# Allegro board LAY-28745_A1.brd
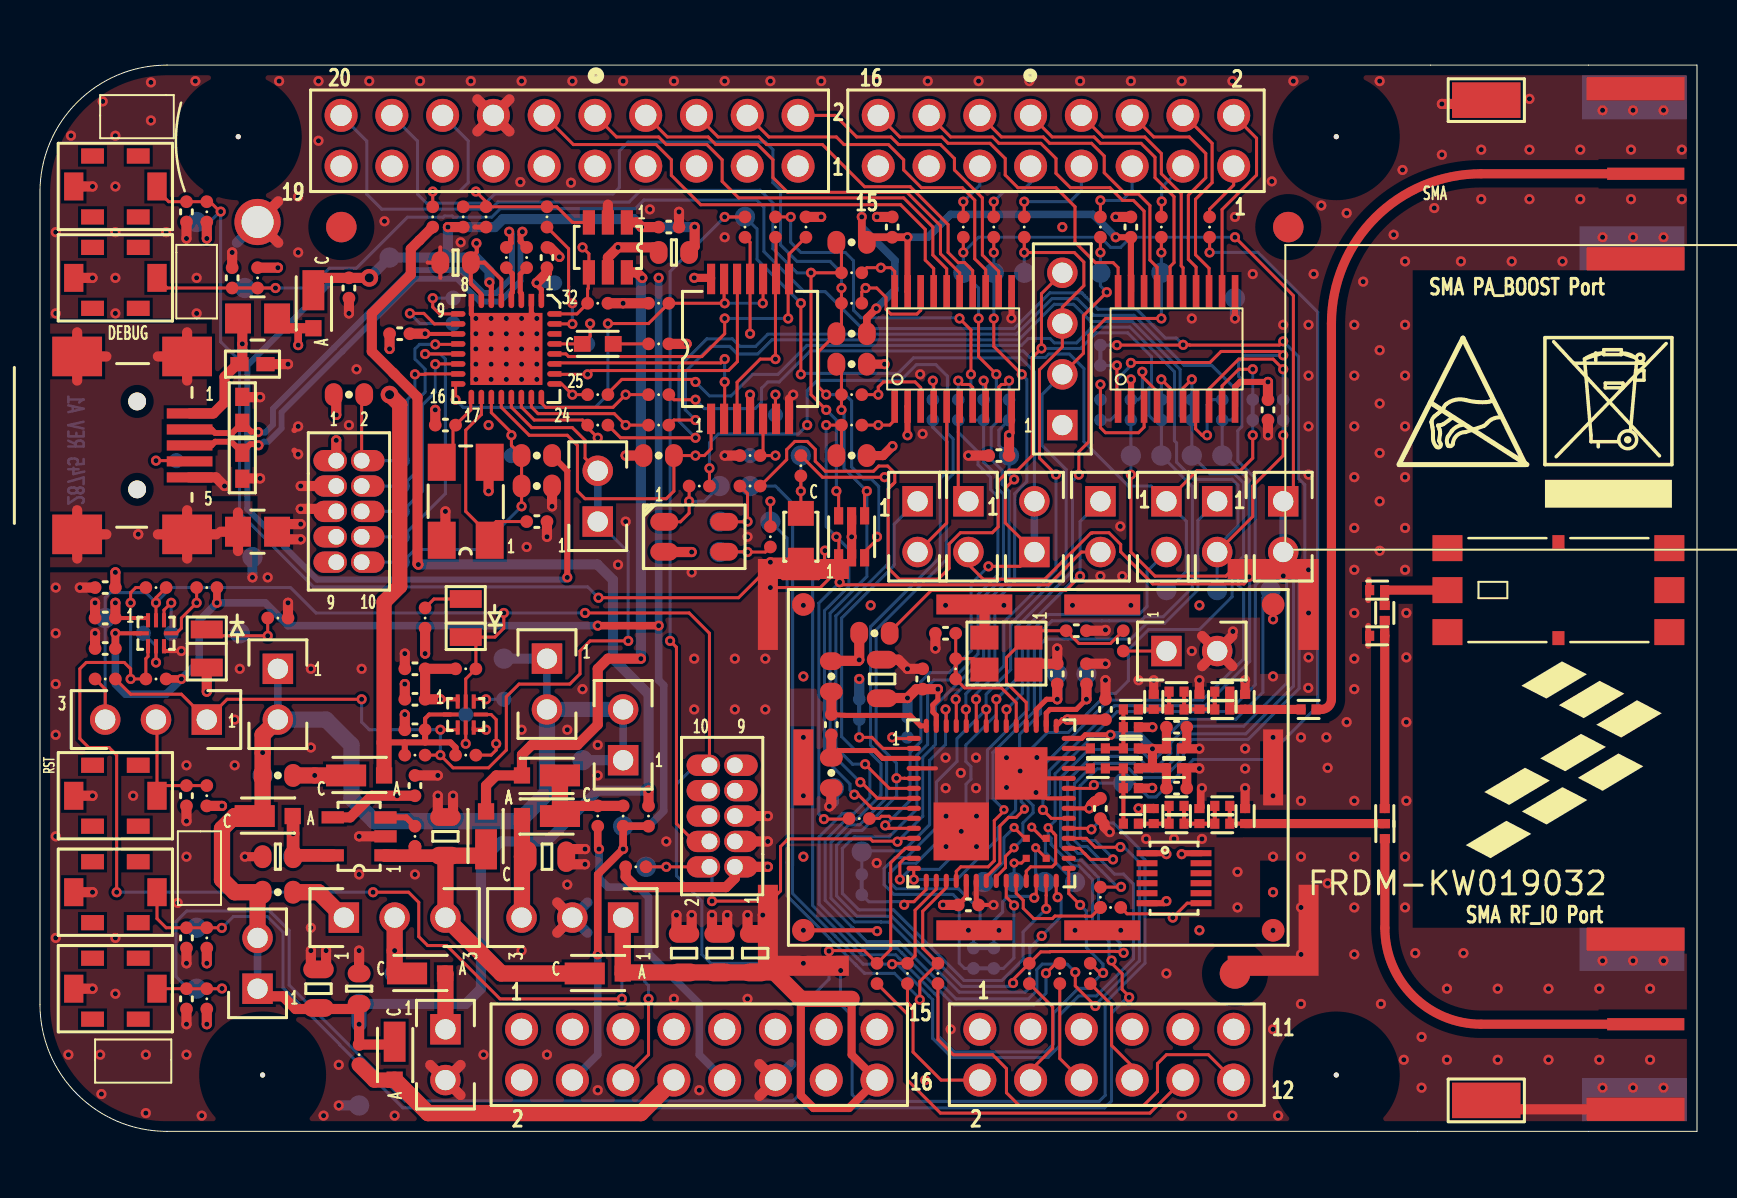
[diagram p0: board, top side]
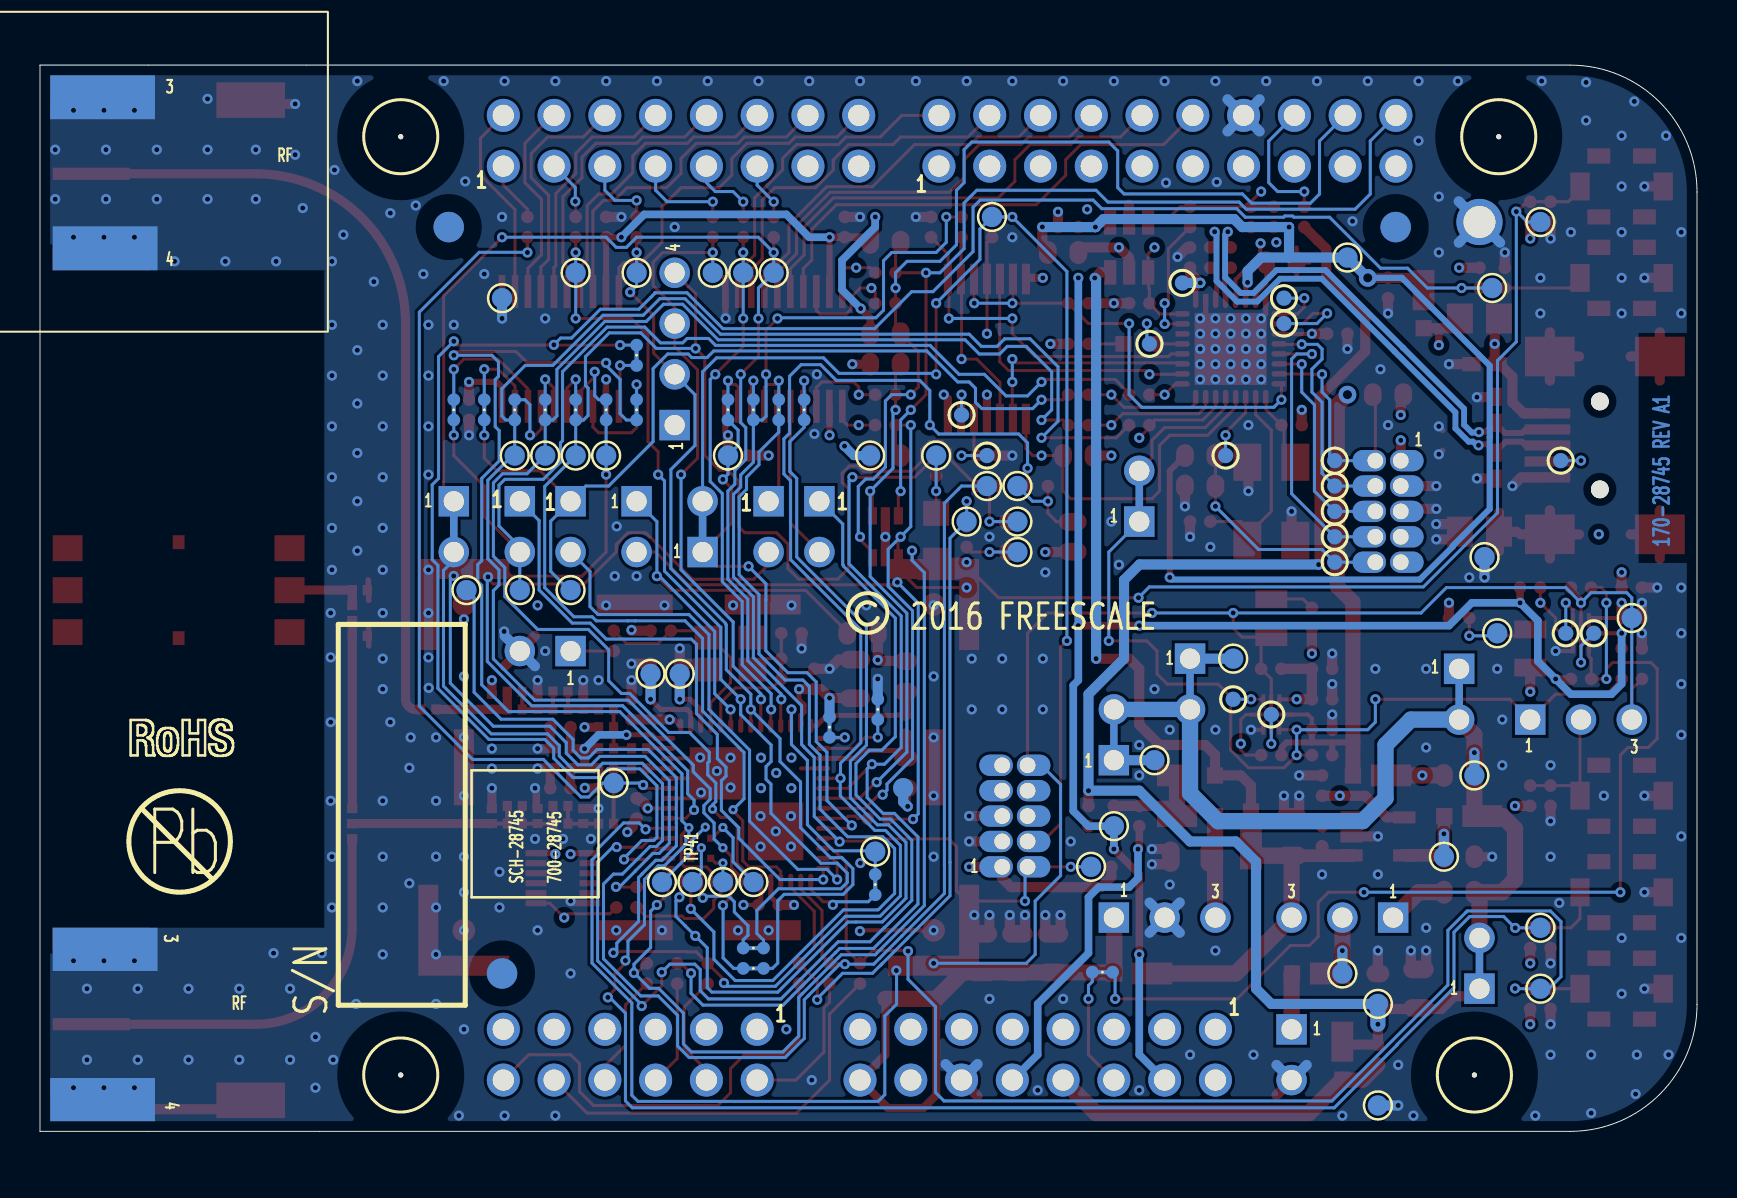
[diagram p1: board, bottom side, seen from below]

Outline 82.89 x 53.34 mm; copper layers: TOP, GND, PWR, BOTTOM. Coordinates in mm from the lower left corner of the outline.
Outline path: 0,46.99 arc(1.86,51.48) 6.35,53.34 82.89,53.34 82.89,0 6.35,0 arc(1.86,1.86) 0,6.35 0,46.99

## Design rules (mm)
net group SDA_USB_CONN_D: nets SDA_USB_CONN_DN SDA_USB_CONN_DP
net group SDA_USB_D: nets SDA_USB_DN SDA_USB_DP
net group GA[0:7]: nets SWD_CLK_TGTMCU
net group GC[0:15]: nets RESET_TGTMCU_B
net group POWER: nets 5V_USB IO_REF N23497733 N23735993 N23818123 N23869363 N23918308 N23977839 N23977884 N23977917 N23977919 N23978170 N23978342 P3V3 P3V3_LDO P5-9V_VIN P5V P5V0_SDA_USB_CONN_VBUS P5V_SDA SDA_USB_VOUT33 SDA_USBSHIELD V_EXT V_MCU VR_ANA VR_DIG VR_PA
net group RF_7CLR: nets N23870337 N23870339 N23870349 N23870369 N23870499 N23870540 RFIO
net group RF_18CLR: nets N23972508 N23972666 N24091032 N24091265 PA_BOOST PA_BOOST_EXT RFIO_EXT

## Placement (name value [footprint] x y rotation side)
ANT1  7488910092  [ANT_7488910092]  75.96 27.08 180 top
C1  10PF  [0402_CC]  59.14 22 180 top
C2  3.3PF  [0402_CC]  60.29 21.49 90 top
C3  6.8PF  [0402_CC]  58 21.49 90 top
C4  5.6PF  [0402_CC]  60.29 15.77 90 top
C5  10UF  [CC0805_OV]  13.93 7.14 90 top
C6  10UF  [CC0805_OV]  35.78 8.92 90 top
C7  10PF  [0402_CC]  59.14 16.28 180 top
C8  10PF  [0402_CC]  56.86 22 180 top
C9  7.5PF  [0402_CC]  58 15.77 90 top
C10  47PF  [0402_CC]  54.57 21.11 0 top
C11  10PF  [0402_CC]  56.86 16.28 180 top
C12  6.8PF  [0402_CC]  54.57 20.22 180 top
C13  6.8PF  [0402_CC]  54.57 15.39 0 top
C14  0.1UF  [CC0402_25]  56.86 17.17 0 top
C15  2.0PF  [0402_CC]  54.57 17.17 0 top
C16  220PF  [0402_CC]  56.73 18.16 0 top
C17  0.01UF  [CC0402_25]  56.86 20.22 0 top
C18  220PF  [0402_CC]  56.73 19.16 0 top
C19  0.1UF  [CC0402_25]  53.05 16.15 270 top
C20  11PF  [CC0402_25]  54.19 24.54 270 top
C21  11PF  [CC0402_25]  51.84 25.04 0 top
C22  11PF  [CC0402_25]  45.3 24.92 180 top
C25  0.1UF  [CC0402_25]  53.3 21.11 90 top
C26  1.0UF  [CC0402_25]  25.36 43.71 90 top
C27  10UF  [CC0805_OV]  42.13 22.63 90 top
C28  0.1UF  [CC0402_25]  50.89 22.89 90 top
C29  4.7UF  [CC0402_25]  18.76 20.09 180 top
C30  22PF  [CC0402_25]  24.85 30.51 0 top
C31  22PF  [CC0402_25]  20.28 35.33 180 top
C32  2.2UF  [CC0603_OV]  20.79 43.46 180 top
C33  0.1UF  [CC0402_25]  31.46 45.24 0 top
C34  18PF  [CC0603_OV]  31.71 43.97 180 top
C35  4.7UF  [CC0402_25]  18.76 23.14 180 top
C36  0.1UF  [CC0402_25]  39.59 20.35 270 top
C37  2.2UF  [CC0603_OV]  15.96 7.14 90 top
C38  10UF  [CC0805_OV]  32.22 8.92 90 top
C39  10UF  [CC0805_OV]  34 8.92 90 top
C40  10UF  [CC0805_OV]  25.36 13.74 0 top
C41  0.1UF  [CC0402_25]  47.97 33.81 180 top
C42  0.1UF  [CC0402_25]  44.16 22.63 90 top
C43  0.01UF  [CC0402_25]  46.44 11.33 0 top
C44  0.1UF  [CC0402_25]  52.35 22.89 90 top
C45  10PF  [0402_CC]  55.71 21.49 90 top
C46  10PF  [0402_CC]  55.71 15.77 90 top
C47  100PF  [0402_CC]  63.46 21.11 0 top
C48  0.1UF  [CC0402_25]  42.63 45.24 90 top
C49  1.0UF  [CC0402_25]  15.46 42.19 270 top
C50  100PF  [0402_CC]  67.27 15.77 90 top
C51  1000PF  [CC0402_25]  7.33 46 270 top
C52  1000PF  [CC0402_25]  7.33 9.68 270 top
C53  1000PF  [CC0402_25]  7.33 6.63 270 top
C54  1000PF  [CC0402_25]  9.61 42.7 90 top
C55  1UF  [CC0805_OV]  20.28 14.76 90 top
C56  470PF  [CC0402_25]  18.76 17.3 90 top
C57  2.2UF  [CC0603_OV]  11.9 13.74 180 top
C58  100PF  [0402_CC]  67.28 15.02 270 top
C59  0.1UF  [CC0402_25]  18.76 21.62 180 top
C60  1000PF  [CC0402_25]  7.33 16.79 270 top
C61  0.1UF  [CC0402_25]  61.43 36.09 270 top
C62  0.1UF  [CC0402_25]  54.57 45.24 90 top
C63  0.1UF  [CC0402_25]  3.26 25.68 180 top
C64  4.7UF  [CC0402_25]  3.26 24.16 180 top
C65  4.7UF  [CC0402_25]  3.26 27.2 180 top
C66  0.1UF  [CC0402_25]  18 39.9 180 top
C67  3.3PF  [0402_CC]  66.89 24.79 180 top
C68  3.3PF  [0402_CC]  66.89 27.08 180 top
D1  MSS1P3L  [SMB_2P7X1P4]  27.9 7.9 0 top
D2  MSS1P3L  [SMB_2P7X1P4]  19.01 7.9 0 top
D3  MSS1P3L  [SMB_2P7X1P4]  11.39 15.77 0 top
D4  RED  [LED0805]  8.34 24.16 0 top
D5  RED  [LED0805]  21.3 25.68 180 top
D6  MSS1P3L  [SMB_2P7X1P4]  25.36 15.77 180 top
D7  MSS1P3L  [SMB_2P7X1P4]  15.96 17.81 0 top
D8  BLUE  [LED2_2P34_2P1X1P25]  38.06 29.74 270 top
D9  MSS1P3L  [SMB_2P7X1P4]  25.36 17.81 180 top
D10  MSS1P3L  [SMB_2P7X1P4]  22.31 14.76 90 top
D11  LED GREEN  [LED_0603]  27.9 39.4 180 top
D12  MSS1P3L  [SMB_2P7X1P4]  17.74 3.84 270 top
D17  CLV1A-FKB-CJ1M1F1BB7R4S3  [LED_CREE_CLV1A_2100UM-MAXHT]  32.73 29.74 0 top
D18  MSS1P3L  [SMB_2P7X1P4]  13.68 41.43 270 top
J1  CON_2x8_0.1"  [MTCONN_JT254F-D180-850-208-10D]  59.72 48.29 180 top
J2  CON_2x10_0.1"  [MTCONN_JT254F-D180-850-210-10D]  37.92 48.29 180 top
J3  CON_2x8_0.1"  [MTCONN_JT254F-D180-850-208-10D]  24.09 5.11 0 top
J4  CON_2x6_0.1"  [MTCONN_JT254F-D180-850-206-10D]  47.02 5.11 0 top
J5  HDR 1X2  [HDR102]  56.35 24.03 90 top
J7  HDR TH 1X3  [HDR103]  29.17 10.69 270 top
J8  HDR TH 1X3  [HDR103]  15.2 10.69 90 top
J9  HDR TH 1X3  [HDR103]  8.34 20.6 270 top
J10  SH HDR 1X2  [HDR102_CT]  62.19 31.52 0 top
J11  SH HDR 1X2  [HDR102_CT]  27.9 30.51 180 top
J13  HDR 2X5  [CON_2RH_10_50]  14.82 33.55 270 top
J14  HDR 2X5  [CON_2RH_10_50]  34.76 13.23 90 top
J15  CONN USB MINI-B  [CON5_USB_RA_SMT]  3.84 34.32 0 top
J18  HDR_1X4  [JUMP1X4-6040]  51.14 35.33 90 top
J28  HDR 1X2  [HDR102]  20.28 5.11 0 top
J31  HDR 1X2  [HDR102]  53.05 31.52 0 top
J35  SH HDR 1X2  [HDR102_CT]  49.75 28.98 180 top
J40  SH HDR 1X2  [HDR102_CT]  25.36 23.65 0 top
J41  HDR 1X2  [HDR102]  58.89 31.52 0 top
J42  HDR 1X2  [HDR102]  56.35 31.52 0 top
J43  HDR 1X2  [HDR102]  46.44 31.52 0 top
J44  HDR 1X2  [HDR102]  43.9 31.52 0 top
J45  SH HDR 1X2  [HDR102_CT]  11.9 23.14 0 top
J46  SH HDR 1X2  [HDR102_CT]  10.88 7.14 180 top
J47  SH HDR 1X2  [HDR102_CT]  29.17 18.57 180 top
J48  SMA  [CON_SMA_EDGE_062]  80.33 47.9 90 top
J49  SMA  [CON_SMA_EDGE_062]  80.33 5.36 90 top
L1  5.6NH  [0402_CC]  59.14 21.11 0 top
L2  0.0068UH  [0402_CC]  59.14 15.39 0 top
L3  5.6NH  [0402_CC]  56.86 21.11 0 top
L4  10NH  [0402_CC]  67.27 25.93 90 top
L5  0.0068UH  [0402_CC]  56.86 15.39 0 top
L6  330 OHM  [IND_0805]  10.88 40.67 0 top
L7  330 OHM  [IND_0805]  10.88 30 0 top
L9  0.0047UH  [0402_CC]  52.92 18.16 0 top
L10  33NH  [0402_CC]  54.57 19.16 180 top
L11  33NH  [0402_CC]  54.57 18.16 180 top
L12  0.002UH  [0402_CC]  52.92 19.16 0 top
NOREF  -  []  310.8 -147.63 0 top
NOREF#2  -  []  75.29 33.36 0 top
NOREF#3  -  []  321.92 -135.69 0 top
NOREF#4  -  []  -411.81 -339.88 0 top
NOREF#5  -  []  314.83 -144.14 0 top
NOREF#6  -  []  320.16 -153.51 0 top
NOREF#7  -  []  68.01 33.36 0 top
NOREF#8  -  [unnamed#2]  15.07 45.24 0 top
NOREF#9  -  []  0 46.99 0 top
NOREF#10  -  []  316.22 -159.04 0 top
NOREF#11  -  [unnamed#2]  59.78 7.9 0 top
NOREF#12  -  []  11.14 2.82 0 top
NOREF#13  -  []  2.5 41.17 0 top
NOREF#14  -  []  -20.4 -36.7 0 top
NOREF#15  -  []  71.32 13.67 0 top
NOREF#16  -  []  148.53 53.62 0 top
NOREF#17  -  []  -40.62 -113.45 0 top
NOREF#18  -  []  82.89 0 90 top
NOREF#19  -  []  320.18 -168.14 0 top
NOREF#20  -  [unnamed#2]  62.45 45.24 0 top
NOREF#21  -  []  -75.62 -129.47 0 top
NOREF#22  -  []  -385.78 185.27 0 top
NOREF#23  -  []  78.45 18.69 180 bottom
NOREF#24  -  [unnamed#2]  11.14 2.82 180 bottom
NOREF#25  -  []  62.13 -0.67 90 bottom
NOREF#26  -  []  75.91 14.25 180 bottom
NOREF#27  -  []  41.36 26.06 180 bottom
NOREF#28  -  [unnamed#2]  64.85 2.82 180 bottom
NOREF#29  -  [unnamed#2]  15.07 45.24 180 bottom
NOREF#30  -  [unnamed#2]  59.78 7.9 180 bottom
NOREF#31  -  [unnamed#2]  9.92 49.76 180 bottom
NOREF#32  -  [unnamed#2]  64.85 49.76 180 bottom
NOREF#33  -  []  102.47 -52.14 270 bottom
NOREF#34  -  []  50.85 12.88 180 bottom
NOREF#35  -  [unnamed#2]  62.45 45.24 180 bottom
NOREF#36  -  []  75.59 16.15 90 bottom
Q1  BSS138PS  [BSS138_DUAL_SC88]  40.6 29.74 0 top
R1  0  [RC0603_OV]  11.9 11.96 180 top
R3  0  [RC0402_25]  18.76 14.76 90 top
R5  4.7K  [RC0603_OV]  41.74 24.92 180 top
R6  0  [RC0603_OV]  11.9 17.81 180 top
R8  0  [RC0603_OV]  39.59 17.93 270 top
R9  0  [RC0603_OV]  39.59 22.76 90 top
R10  220  [RC0402_25]  11.9 25.68 0 top
R11  220  [RC0402_25]  32.98 32.28 0 top
R12  0  [RC0402_25]  35.52 33.81 180 top
R13  180K  [RC0402_25]  21.3 23.14 0 top
R14  0  [RC0402_25]  3.26 22.63 180 top
R16  10.0K  [RC0402_25]  18.76 18.82 0 top
R17  220  [RC0402_25]  30.95 39.4 180 top
R18  220  [RC0402_25]  19.27 25.68 270 top
R19  10.0K  [RC0402_25]  21.3 18.82 180 top
R20  10.0K  [RC0402_25]  8.34 27.2 0 top
R21  10.0K  [RC0402_25]  5.8 22.63 180 top
R25  10.0K  [RC0402_25]  29.81 13.23 180 top
R28  220  [RC0402_25]  35.52 32.28 0 top
R29  220  [RC0402_25]  36.54 29.74 90 top
R30  220  [RC0402_25]  38.06 33.3 90 top
R50  33  [RC0402_25]  23.33 43.71 270 top
R51  33  [RC0402_25]  24.35 43.71 270 top
R52  4.7K  [RC0603_OV]  24.85 33.81 180 top
R85  100  [RC0402_25]  40.98 15.65 180 top
R88  1.0K  [RC0402_25]  30.95 36.86 0 top
R89  1.0K  [RC0402_25]  27.9 36.86 0 top
R90  1.0K  [RC0402_25]  27.9 35.33 0 top
R91  1.0K  [RC0402_25]  30.95 35.33 0 top
R92  1.0K  [RC0402_25]  36.79 45.24 90 top
R93  1.0K  [RC0402_25]  35.27 45.24 90 top
R96  0  [RC0402_25]  53.56 11.2 0 top
R97  0  [RC0402_25]  53.05 11.71 90 top
R100  10K  [RC0603_OV]  24.85 32.28 0 top
R105  10K  [RC0603_OV]  30.95 33.81 180 top
R106  27K  [RC0402_25]  30.95 41.43 0 top
R107  10K  [RC0603_OV]  15.46 36.86 0 top
R108  10.0K  [RC0402_25]  21.17 45.75 90 top
R109  15K  [RC0402_25]  22.31 45.75 270 top
R110  10.0K  [RC0402_25]  27.9 41.43 180 top
R112  27K  [RC0402_25]  38.32 45.24 90 top
R113  15K  [RC0402_25]  8.34 16.79 90 top
R116  4.7K  [RC0603_OV]  40.6 33.81 180 top
R117  4.7K  [RC0603_OV]  40.6 38.38 180 top
R118  0  [RC0402_25]  40.6 35.33 0 top
R119  0  [RC0402_25]  40.6 36.86 0 top
R120  0  [RC0402_25]  40.6 42.95 180 top
R121  0  [RC0402_25]  40.6 41.43 180 top
R122  0  [RC0402_25]  56.1 45.24 90 top
R123  0  [RC0402_25]  53.05 45.24 90 top
R124  0  [RC0402_25]  5.8 27.2 180 top
R125  4.7K  [RC0603_OV]  40.6 44.48 180 top
R126  4.7K  [RC0603_OV]  40.6 39.9 180 top
R127  0  [RC0402_25]  15.96 3.84 270 top
R128  0  [RC0402_25]  19.65 45.75 270 top
R129  0  [RC0402_25]  49.24 45.24 90 top
R130  0  [RC0402_25]  47.71 45.24 90 top
R131  0  [RC0402_25]  46.19 45.24 90 top
R132  0  [RC0402_25]  44.92 7.9 270 top
R133  0  [RC0402_25]  41.87 7.9 270 top
R134  0  [RC0402_25]  52.54 7.9 270 top
R135  0  [RC0402_25]  51.02 7.9 270 top
R136  0  [RC0402_25]  43.4 7.9 270 top
R137  0  [RC0402_25]  49.49 7.9 270 top
R138  0  [RC0402_25]  30.44 15.77 90 top
R139  0  [RC0402_25]  29.17 15.77 90 top
R140  0  [RC0402_25]  27.9 15.77 270 top
R141  0  [RC0402_25]  58.51 45.24 90 top
R551  1.0K  [RC0402_25]  25.36 45.75 90 top
R556  10.0K  [RC0402_25]  8.34 46 90 top
R557  10.0K  [RC0402_25]  8.34 9.68 90 top
R558  10.0K  [RC0402_25]  8.34 6.63 90 top
R559  10.0K  [RC0402_25]  10.88 42.7 270 top
S1  RF SHIELD  [RF_SHIELD_KW01]  38.19 10.06 0 top
SH1  0  [RC0402_25_CT]  48.48 36.09 270 bottom
SH3  0  [RC0402_25_CT]  45.94 36.09 270 bottom
SH6  0  [RC0402_25_CT]  44.67 36.09 270 bottom
SH7  0  [RC0402_25_CT]  47.21 36.09 270 bottom
SH8  0  [RC0402_25_CT]  53.05 38.82 90 bottom
SH9  0  [RC0402_25_CT]  53.05 36.09 270 bottom
SH10  0  [RC0402_25_CT]  54.57 36.09 270 bottom
SH11  0  [RC0402_25_CT]  56.1 36.09 270 bottom
SH12  0  [RC0402_25_CT]  57.62 36.09 270 bottom
SH13  0  [RC0402_25_CT]  29.74 7.96 180 bottom
SH14  0  [RC0402_25_CT]  59.14 36.09 270 bottom
SH15  0  [RC0402_25_CT]  62.19 36.09 270 bottom
SH16  0  [RC0402_25_CT]  60.67 36.09 270 bottom
SH40  0  [RC0402_25_CT]  47.21 9.17 0 bottom
SH41  0  [RC0402_25_CT]  47.21 8.15 0 bottom
SH42  0  [RC0402_25_CT]  43.4 20.22 270 bottom
SH43  0  [RC0402_25_CT]  40.98 21.11 270 bottom
SH44  0  [RC0402_25_CT]  45.81 23.14 90 top
SH45  0  [RC0402_25_CT]  41.11 12.34 270 bottom
SW1  TL1015AF160QG  [SW2_2MM]  3.77 47.27 180 top
SW2  TL1015AF160QG  [SW2_2MM]  3.77 42.7 180 top
SW3  TL1015AF160QG  [SW2_2MM]  3.77 11.96 180 top
SW4  TL1015AF160QG  [SW2_2MM]  3.77 7.14 180 top
SW5  TL1015AF160QG  [SW2_2MM]  3.77 16.79 180 top
TL1  TESTLOOP  [TESTPOINT_135_070MIL]  72.35 1.55 180 top
TL2  TESTLOOP  [TESTPOINT_135_070MIL]  72.35 51.59 180 top
TP2  -  [TPAD_040]  12.66 13.74 180 bottom
TP3  -  [TPAD_030]  21.3 20.85 180 bottom
TP4  -  [TPAD_040]  41.36 33.81 180 bottom
TP5  -  [TPAD_030]  23.2 21.62 180 bottom
TP6  -  [TPAD_040]  23.2 23.65 180 bottom
TP7  -  [TPAD_040]  15.96 6.38 180 bottom
TP8  -  [TPAD_040]  9.99 24.92 180 bottom
TP9  -  [TPAD_040]  15.96 1.3 180 bottom
TP10  -  [TPAD_040]  59.78 41.68 180 bottom
TP11  -  [TPAD_040]  39.71 17.17 180 bottom
TP12  -  [TPAD_040]  10.63 28.73 180 bottom
TP13  -  [TPAD_040]  27.14 18.57 180 bottom
TP14  -  [TPAD_030]  5.17 24.92 180 bottom
TP15  -  [TPAD_030]  6.57 24.92 180 bottom
TP17  -  [TPAD_040]  38.06 33.81 180 bottom
TP18  -  [TPAD_040]  34 32.28 180 bottom
TP19  -  [TPAD_040]  34 30.51 90 bottom
TP20  -  [TPAD_040]  34 28.98 180 bottom
TP23  -  [TPAD_040]  7.84 45.49 180 bottom
TP24  -  [TPAD_040]  7.84 10.19 180 bottom
TP29  -  [TPAD_040]  7.84 7.14 180 bottom
TP30  -  [TPAD_040]  10.25 42.19 180 bottom
TP31  -  [TPAD_040]  11.14 17.81 180 bottom
TP32  -  [TPAD_040]  30.31 13.23 180 bottom
TP33  -  [TPAD_040]  17.74 7.9 180 bottom
TP35  -  [TPAD_040]  3.26 25.68 180 bottom
TP36  -  [TPAD_040]  48.48 33.81 180 bottom
TP37  -  [TPAD_040]  54.19 17.42 180 bottom
TP38  -  [TPAD_040]  48.73 12.47 180 bottom
TP39  -  [TPAD_040]  47.21 12.47 180 bottom
TP40  -  [TPAD_040]  51.78 12.47 180 bottom
TP41  -  [TPAD_040]  50.25 12.47 180 bottom
TP42  -  [TPAD_040]  41.11 14 180 bottom
TP43  -  [TPAD_040]  46.19 42.95 180 bottom
TP44  -  [TPAD_040]  47.71 42.95 180 bottom
TP45  -  [TPAD_040]  49.24 42.95 180 bottom
TP46  -  [TPAD_040]  52.35 22.89 180 bottom
TP47  -  [TPAD_040]  53.05 42.95 180 bottom
TP48  -  [TPAD_040]  50.89 22.89 180 bottom
TP49  -  [TPAD_040]  56.1 42.95 180 bottom
TP51  -  [TPAD_040]  35.27 45.75 180 bottom
TP100  -  [TPAD_030]  6.82 33.55 180 bottom
TP101  -  [TPAD_030]  20.66 41.68 90 bottom
TP102  -  [TPAD_030]  20.66 40.41 90 bottom
TP103  -  [TPAD_030]  25.74 42.44 90 bottom
TP104  -  [TPAD_040]  17.49 43.71 180 bottom
TP105  -  [TPAD_030]  23.58 33.81 180 bottom
TP106  -  [TPAD_030]  27.39 39.4 180 bottom
TP107  -  [TPAD_030]  35.52 33.81 180 bottom
TP108  -  [TPAD_030]  36.79 35.84 180 bottom
TP112  -  [TPAD_040]  54.57 33.81 180 bottom
TP113  -  [TPAD_040]  58.89 27.08 180 bottom
TP114  -  [TPAD_040]  56.35 27.08 180 bottom
TP115  -  [TPAD_040]  35.52 32.28 180 bottom
TP119  -  [TPAD_040]  61.56 27.08 180 bottom
TP120  -  [TPAD_040]  36.54 30.51 180 bottom
TP121  -  [TPAD_040]  56.1 33.81 180 bottom
TP122  -  [TPAD_040]  59.14 33.81 180 bottom
TP123  -  [TPAD_040]  57.62 33.81 180 bottom
TP124  -  [TPAD_040]  29.17 15.27 180 bottom
TP507  TESTLOOP_BLACK  [TP_TH_063]  10.88 45.49 0 top
TP508  -  [TPAD_030]  18.12 33.55 180 bottom
TP509  -  [TPAD_030]  18.12 32.28 180 bottom
TP510  -  [TPAD_030]  18.12 31.01 180 bottom
TP511  -  [TPAD_030]  18.12 29.74 180 bottom
TP512  -  [TPAD_030]  18.12 28.47 180 bottom
U1  MKW01Z128  [LGA60_0P5_8X8]  47.59 16.41 0 top
U3  NTSX2102GU8H  [XQFN8_1P45X1P25MM]  21.3 20.85 0 top
U4  74LVC125ADB  [SSOP14]  35.52 39.14 90 top
U5  NTSX2102GU8H  [XQFN8_1P45X1P25MM]  5.8 24.92 0 top
U6  MK20DX128VFM5  [QFN32_S142EP]  23.33 39.14 270 top
U7  MIC2005-0.8YM6  [SOT23-6_A]  28.41 44.22 270 top
U10  0402ESDA-MLP  [0402_MLP]  10.63 38.38 0 top
U11  0402ESDA-MLP  [0402_MLP]  10.12 33.3 270 top
U12  0402ESDA-MLP  [0402_MLP]  10.12 36.09 90 top
U16  TXB0108  [TI_PW_TSSOP20]  45.68 39.14 90 top
U17  TXB0108  [TI_PW_TSSOP20]  56.86 39.14 90 top
U18  MIC5205-3.3  [SOT23-5]  15.96 14.76 90 top
Y1  32MHZ  [XTLOSC4_3P2X2P5MM_SM]  48.35 23.9 180 top
Y3  8MHZ  [XTLOSC4_5X3MM_SM]  21.3 31.52 90 top
Y4  32.768KHZ  [XTAL_SG-30X0LC]  56.73 12.66 0 top

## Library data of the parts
ANT1 = ANT_Wurth_7488910092
C1 C7 C8 C11 C34 C45 C46 = CAP_NP: tolerance: 5%
C2-C6 C9 C10 C12-C22 C25-C28 C30-C33 C36 C38-C44 C47-C56 C58-C63 C66-C68 = CAP_NP
C29 C35 C37 C57 C64 C65 = CAP_NP: tolerance: 10%
D1-D3 D6 D7 D9 D10 D12 D18 = DIODE_SCHTKY
D4 D5 D8 D11 = LED
D17 = LED_RGB_CREE
J1 J3 = CONN_2x8_MTCONN
J2 = CONN_2x10_MTCONN
J4 = CONN_2x6_MTCONN
J5 J28 J31 J41-J44 = CONN_HDR_2X1
J7-J9 = CONN_HDR_3X1
J10 J11 J35 J40 J45-J47 = CONN_HDR_2X1_CT
J13 J14 = CONN_HDR_5X2: User Part Number: XXX-XXXXX-00
J15 = USB_MINI_AB_RECEPTACLE
J18 = HDR-1X4
J48 J49 = SMB
L1 L3 = INDP
L2 L4 L5 L9-L12 = INDUCTOR
L6 L7 = BEAD
Q1 = BSS138PS_DUAL
R1 R3 R5 R6 R8-R13 R17 R18 R28-R30 R50-R52 R85 R96 R97 R100 R105-R107 R112 R116-R141 = RES
R14 R16 R19-R21 = RES: tolerance: 5%
R25 R88-R93 R108-R110 R113 R551 R556-R559 = RES: tolerance: 1%
S1 = RF_SHIELD_CUSTOM
SH1 SH3 SH6-SH16 SH40-SH45 = SH_RES
SW1-SW5 = SW_TACT-SPST-2_SMD
TL1 TL2 TP2 TP4 TP6-TP13 TP17-TP20 TP23 TP24 TP29-TP33 TP35-TP49 TP51 TP104 TP112-TP115 TP119-TP124 TP507 = TestLoop
TP3 TP5 TP14 TP15 TP100-TP103 TP105-TP108 TP508-TP512 = TESTLOOP
U1 = MKW01Z128_LGA_0
U3 U5 = NTSX2102GU8H_8P
U4 = 74-125_14P
U6 = PK20DX128V_QFN_32P
U7 = MIC2005-0_0.8YM6
U10-U12 = DIODE_TVS_BIDIR
U16 U17 = TXB0108: User Part Number: ***; Tolerance: ***
U18 = MIC5205-3V3_SOT23-5
Y1 = XTAL_13Y
Y3 = CRYSTAL_JXS63
Y4 = XTAL_SG-30x0LC_0

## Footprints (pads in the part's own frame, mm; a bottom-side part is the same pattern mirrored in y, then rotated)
0402_CC
  rect 0.457x0.508 smd: 1(-0.375,0) 2(0.375,0)
0402_MLP
  rect 0.914x0.711 smd: 1(-0.65,0) 2(0.65,0)
ANT_7488910092
  rect 1.5x1.3 smd: (-5.55,2.1) (-5.55,0) (-5.55,-2.1) (5.55,2.1) (5.55,-2.1) 2(5.55,0)
  rect 0.6x0.7 smd: (0,2.4) (0,-2.4)
BSS138_DUAL_SC88
  rect 0.457x0.864 smd: D1(-0.65,1.05) D2(0.65,-1.05) G1(0,-1.05) G2(0,1.05) S1(-0.65,-1.05) S2(0.65,1.05)
CC0402_25
  round 0.635 smd: 1(-0.508,0) 2(0.508,0)
CC0603_OV
  oval 0.889x1.143 smd: 1(-0.762,0) 2(0.762,0)
CC0805_OV
  oval 0.889x1.524 smd: 1(-0.965,0) 2(0.965,0)
CON5_USB_RA_SMT
  round 0.889 hole 0.889 unplated: (1.025,2.2) (1.025,-2.2)
  rect 2.286x0.508 smd: 1(3.65,1.6) 2(3.65,0.8) 3(3.65,0) 4(3.65,-0.8) 5(3.65,-1.6)
  rect 2.489x1.981 smd: S1(3.525,4.45) S2(3.525,-4.45) S3(-1.975,4.45) S4(-1.975,-4.45)
CON_2RH_10_50
  oval 1.067x1.676 hole 0.787: 1(0,0) 2(0,1.27) 3(1.27,0) 4(1.27,1.27) 5(2.54,0) 6(2.54,1.27) 7(3.81,0) 8(3.81,1.27) 9(5.08,0) 10(5.08,1.27)
CON_SMA_EDGE_062
  rect 0.61x3.861 smd: 1(0,0)
  rect 1.143x4.877 smd: 2(4.255,0.508) 3(4.255,0.508) 4(-4.255,0.508) 5(-4.255,0.508)
HDR102
  rect 1.524x1.524 hole 1.016: 1(0,0)
  round 1.524 hole 1.016: 2(0,-2.54)
HDR102_CT
  rect 1.524x1.524 hole 1.016: 1(0,0)
  round 1.524 hole 1.016: 2(0,-2.54)
HDR103
  rect 1.524x1.524 hole 1.016: 1(0,0)
  round 1.524 hole 1.016: 2(0,-2.54) 3(0,-5.08)
IND_0805
  rect 1.295x1.499 smd: 1(-0.978,0) 2(0.978,0)
JUMP1X4-6040
  rect 1.524x1.524 hole 1.016: 1(0,0)
  round 1.524 hole 1.016: 2(2.54,0) 3(5.08,0) 4(7.62,0)
LED2_2P34_2P1X1P25
  rect 1.245x1.295 smd: A(1.172,0) C(-1.172,0)
LED0805
  rect 1.6x0.889 smd: A(0,-0.953) C(0,0.953)
LED_0603
  rect 0.838x0.787 smd: A(-0.775,0) C(0.775,0)
LED_CREE_CLV1A_2100UM-MAXHT
  oval 1.397x0.889 smd: 1(-1.499,0.749) 2(-1.499,-0.749) 3(1.499,-0.749) 4(1.499,0.749)
LGA60_0P5_8X8
  oval 0.711x0.254 smd: 1(-3.878,3.25) 2(-3.878,2.75) 3(-3.878,2.25) 4(-3.878,1.75) 5(-3.878,1.25) 6(-3.878,0.75) 7(-3.878,0.25) 8(-3.878,-0.25) 9(-3.878,-0.75) 10(-3.878,-1.25) 11(-3.878,-1.75) 12(-3.878,-2.25) 13(-3.878,-2.75) 14(-3.878,-3.25) 29(3.878,-3.25) 30(3.878,-2.75) 31(3.878,-2.25) 32(3.878,-1.75) 33(3.878,-1.25) 34(3.878,-0.75) 35(3.878,-0.25) 36(3.878,0.25) 37(3.878,0.75) 38(3.878,1.25) 39(3.878,1.75) 40(3.878,2.25) 41(3.878,2.75) 42(3.878,3.25)
  oval 0.254x0.711 smd: 15(-3.25,-3.878) 16(-2.75,-3.878) 17(-2.25,-3.878) 18(-1.75,-3.878) 19(-1.25,-3.878) 20(-0.75,-3.878) 21(-0.25,-3.878) 22(0.25,-3.878) 23(0.75,-3.878) 24(1.25,-3.878) 25(1.75,-3.878) 26(2.25,-3.878) 27(2.75,-3.878) 28(3.25,-3.878) 43(3.25,3.878) 44(2.75,3.878) 45(2.25,3.878) 46(1.75,3.878) 47(1.25,3.878) 48(0.75,3.878) 49(0.25,3.878) 50(-0.25,3.878) 51(-0.75,3.878) 52(-1.25,3.878) 53(-1.75,3.878) 54(-2.25,3.878) 55(-2.75,3.878) 56(-3.25,3.878)
  rect 0.356x0.356 smd: 57(1.75,-1.75) 58(2.75,-1.75) 59(1.75,-2.75) 60(2.75,-2.75)
  rect 2.769x2.896 smd: 61(-1.5,-1.4)
  rect 2.616x2.616 smd: 62(1.5,1.5)
MTCONN_JT254F-D180-850-206-10D
  round 1.651 hole 1.067: 1(0,0) 2(0,-2.54) 3(2.54,0) 4(2.54,-2.54) 5(5.08,0) 6(5.08,-2.54) 7(7.62,0) 8(7.62,-2.54) 9(10.16,0) 10(10.16,-2.54) 11(12.7,0) 12(12.7,-2.54)
MTCONN_JT254F-D180-850-208-10D
  round 1.651 hole 1.067: 1(0,0) 2(0,-2.54) 3(2.54,0) 4(2.54,-2.54) 5(5.08,0) 6(5.08,-2.54) 7(7.62,0) 8(7.62,-2.54) 9(10.16,0) 10(10.16,-2.54) 11(12.7,0) 12(12.7,-2.54) 13(15.24,0) 14(15.24,-2.54) 15(17.78,0) 16(17.78,-2.54)
MTCONN_JT254F-D180-850-210-10D
  round 1.651 hole 1.067: 1(0,0) 2(0,-2.54) 3(2.54,0) 4(2.54,-2.54) 5(5.08,0) 6(5.08,-2.54) 7(7.62,0) 8(7.62,-2.54) 9(10.16,0) 10(10.16,-2.54) 11(12.7,0) 12(12.7,-2.54) 13(15.24,0) 14(15.24,-2.54) 15(17.78,0) 16(17.78,-2.54) 17(20.32,0) 18(20.32,-2.54) 19(22.86,0) 20(22.86,-2.54)
QFN32_S142EP
  custom 0.07x0.07 smd: 1(-2.4,1.751) 2(-2.4,1.251) 3(-2.4,0.751) 4(-2.4,0.25) 5(-2.4,-0.25) 6(-2.4,-0.751) 7(-2.4,-1.251) 8(-2.4,-1.751) 9(-1.751,-2.4) 10(-1.251,-2.4) 11(-0.751,-2.4) 12(-0.25,-2.4) 13(0.25,-2.4) 14(0.751,-2.4) 15(1.251,-2.4) 16(1.751,-2.4) 17(2.4,-1.751) 18(2.4,-1.251) 19(2.4,-0.751) 20(2.4,-0.25) 21(2.4,0.25) 22(2.4,0.751) 23(2.4,1.251) 24(2.4,1.751) 25(1.751,2.4) 26(1.251,2.4) 27(0.751,2.4) 28(0.25,2.4) 29(-0.25,2.4) 30(-0.751,2.4) 31(-1.251,2.4) 32(-1.751,2.4)
  rect 3.607x3.607 smd: 33(0,0)
RC0402_25
  round 0.635 smd: 1(-0.508,0) 2(0.508,0)
RC0402_25_CT
  round 0.635 smd: 1(-0.508,0) 2(0.508,0)
RC0603_OV
  oval 0.889x1.143 smd: 1(-0.762,0) 2(0.762,0)
RF_SHIELD_KW01
  custom 1.138x1.138 smd: 1(0,0) 3(0,16.3) 6(23.5,16.3) 8(23.5,0)
  rect 1x3.8 smd: 2(0,8.15) 7(23.5,8.15)
  rect 3.8x1 smd: 4(8.55,16.3) 5(14.95,16.3) 9(14.95,0) 10(8.55,0)
SMB_2P7X1P4
  rect 0.813x0.813 smd: A(1.25,0)
  rect 2.007x1.092 smd: C(-0.65,0)
SOT23-5
  rect 0.61x1.118 smd: 1(-0.95,-1.321) 2(0,-1.321) 3(0.95,-1.321) 4(0.95,1.321) 5(-0.95,1.321)
SOT23-6_A
  rect 1.219x0.61 smd: 1(-1.25,0.95) 2(-1.25,0) 3(-1.25,-0.95) 4(1.25,-0.95) 5(1.25,0) 6(1.25,0.95)
SSOP14
  rect 1.524x0.406 smd: 1(-3.5,1.95) 2(-3.5,1.3) 3(-3.5,0.65) 4(-3.5,0) 5(-3.5,-0.65) 6(-3.5,-1.3) 7(-3.5,-1.95) 8(3.5,-1.95) 9(3.5,-1.3) 10(3.5,-0.65) 11(3.5,0) 12(3.5,0.65) 13(3.5,1.3) 14(3.5,1.95)
SW2_2MM
  rect 1.143x0.762 smd: (-1.143,1.524) (-1.143,-1.524) (1.143,1.524) (1.143,-1.524)
  rect 0.965x1.397 smd: 1(-2.083,0) 2(2.083,0)
TESTPOINT_135_070MIL
  rect 3.429x1.778 smd: 1(0,0)
TI_PW_TSSOP20
  rect 1.651x0.33 smd: 1(-2.87,2.926) 2(-2.87,2.276) 3(-2.87,1.626) 4(-2.87,0.975) 5(-2.87,0.325) 6(-2.87,-0.325) 7(-2.87,-0.975) 8(-2.87,-1.626) 9(-2.87,-2.276) 10(-2.87,-2.926) 11(2.87,-2.926) 12(2.87,-2.276) 13(2.87,-1.626) 14(2.87,-0.975) 15(2.87,-0.325) 16(2.87,0.325) 17(2.87,0.975) 18(2.87,1.626) 19(2.87,2.276) 20(2.87,2.926)
TP_TH_063
  round 2.311 hole 1.6: 1(0,0)
TPAD_030
  round 0.762 smd: 1(0,0)
TPAD_040
  round 1.016 smd: 1(0,0)
unnamed#2
  round 1.524 smd: (0,0)
XQFN8_1P45X1P25MM
  rect 0.787x0.203 smd: 1(-0.75,0)
  rect 0.203x0.711 smd: 2(-0.4,-0.65) 3(0,-0.65) 4(0.4,-0.65) 6(0.4,0.65) 7(0,0.65) 8(-0.4,0.65)
  rect 0.711x0.203 smd: 5(0.75,0)
XTAL_SG-30X0LC
  rect 1.041x0.305 smd: 1(-1.35,1.25) 2(-1.35,0.75) 3(-1.35,0.25) 4(-1.35,-0.25) 5(-1.35,-0.75) 6(-1.35,-1.25) 7(1.35,-1.25) 8(1.35,-0.75) 9(1.35,-0.25) 10(1.35,0.25) 11(1.35,0.75) 12(1.35,1.25)
XTLOSC4_3P2X2P5MM_SM
  rect 1.397x1.194 smd: 1(-1.1,-0.8) 2(1.1,-0.8) 3(1.1,0.8) 4(-1.1,0.8)
XTLOSC4_5X3MM_SM
  rect 1.854x1.397 smd: 1(-1.95,-1.2) 2(1.95,-1.2) 3(1.95,1.2) 4(-1.95,1.2)

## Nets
5V_USB: D9.A D10.A U7.6(VOUT)
GND: C2.2 C3.2 C4.2 C5.2 C6.2 C9.2 C12.1 C14.2 C15.2 C16.2 C17.2 C18.2 C19.2 C21.2 C22.2 C25.2 C26.2 C27.2 C28.2 C29.2 C30.2 C31.2 C32.2 C33.2 C35.2 C37.2 C38.2 C39.2 C40.2 C41.2 C42.2 C43.2 C44.2 C45.2 C46.2 C48.2 C49.2 C51.2 C52.2 C53.2 C54.2 C55.2 C56.2 C57.2 C59.2 C60.2 C61.2 C62.2 C63.2 C64.2 C65.2 C66.2 C67.2 C68.2 J2.14(B7) J3.12(B6) J3.14(B7) J5.2 J7.2 J13.3(A2) J13.5(A3) J14.3(A2) J14.5(A3) J15.5(P5) J18.1 J28.2 J48.2(SHIELD2) J48.3(SHIELD1) J48.4(SHIELD3) J48.5(SHIELD4) J49.2(SHIELD2) J49.3(SHIELD1) J49.4(SHIELD3) J49.5(SHIELD4) L7.2 R8.2 R10.2 R12.2 R100.2 R109.2 R112.2 S1.1 S1.2 S1.3 S1.4 S1.5 S1.6 S1.7 S1.8 S1.9 S1.10 SH43.1 SW1.2 SW2.2 SW3.2 SW4.2 SW5.2 TL1.1(PIN1) TL2.1(PIN1) TP9.1(PIN1) TP10.1(PIN1) TP11.1(PIN1) TP12.1(PIN1) TP507.1(PIN1) U1.4(VSS1#4) U1.20(VSS1#20) U1.36(GND/SCAN) U1.38(GND_PA2) U1.40(GND_PA1) U1.61(FLAG1) U1.62(FLAG2) U3.4(GND) U4.7(GND) U5.4(GND) U6.2(VSS1) U6.8(VSSA) U6.33(EPAD) U7.2(GND) U10.2(A2) U11.2(A2) U12.2(A2) U16.11(GND) U17.11(GND) U18.2(GND) Y1.2 Y1.4 Y3.2(GND1) Y3.4(GND2) Y4.6(GND)
P3V3: C5.1 C37.1 D12.C J46.1 R127.1 R128.2 R138.2 TP7.1(PIN1)
P3V3_BRD: C41.1 C61.1 C63.1 C65.1 D4.A(ANODE) D8.A(ANODE) D17.2(BLUE_C) J45.1 Q1.G1(G2) Q1.G2 R116.1 R117.1 R556.1 R557.1 R558.1 R559.1 TP4.1(PIN1) U5.8(VCCB) U16.2(VCCA) U16.10(OE) U17.2(VCCA) U17.10(OE)
P3V3_LDO: C57.1 D3.A TP2.1(PIN1) U18.5(VOUT)
P5V: D6.C D9.C R139.2 R140.1
P5V0_SDA_USB_CONN_VBUS: J15.1(P1) L6.1 U10.1(A1)
P5V_SDA: C33.1 C34.1 C49.1 D18.C R52.1 R108.1 TP104.1(PIN1) U6.6(VREGIN) U7.1(VIN)
VSSA: C36.2 R8.1 U1.3(VSSA)
A1/INT: J4.4(B2) R137.2
A2/INT: J4.6(B3) R135.2
A3/INT: J4.8(B4) R134.2
A4/SDA/INT: J4.10(B5) R133.2
A5/SCL/INT: J4.12(B6) R132.2
D0/RX/INT: J1.2(B1) U17.12(B8)
D1/TX/INT: J1.4(B2) U17.13(B7)
D2/INT: J1.6(B3) U17.14(B6)
D3/PWM/INT: J1.8(B4) U17.15(B5)
D4/INT: J1.10(B5) U17.16(B4)
D5/PWM/INT: J1.12(B6) U17.17(B3)
D6/PWM/INT: J1.14(B7) U17.18(B2)
D7/CMP/INT: J1.16(B8) U17.20(B1)
D8/INT: J2.2(B1) U16.12(B8)
D9/INT: J2.4(B2) U16.13(B7)
D10/SPI_SS: J2.6(B3) U16.14(B6)
D11/MOSI: J2.8(B4) U16.15(B5)
D12/MISO: J2.10(B5) U16.16(B4)
D13/SCK: J2.12(B6) U16.17(B3)
DIO0: R122.1 SH40.1 TP49.1(PIN1) U1.49(DIO0/PTE2)
DIO1: J18.2 R123.1 SH41.1 TP47.1(PIN1) U1.50(DIO1/PTE3)
DIO2: J18.3 R129.1 TP45.1(PIN1) U1.51(DIO2)
DIO3: R130.1 TP44.1(PIN1) U1.52(DIO3)
DIO4: J10.1 R131.1 TP43.1(PIN1) U1.53(DIO4)
DIO5/CLKOUT: SH45.1 TP42.1(PIN1) U1.54(DIO5/CLKOUT)
EXTAL_32M: C20.1 C21.1 U1.46(XTA) Y1.1
IO_REF: C48.1 C62.1 C64.1 J3.4(B2) R20.2 R21.1 R125.1 R126.1 R138.1 R139.1 TP124.1(PIN1) U5.1(VCCA) U16.19(VCCB) U17.19(VCCB)
P5-9V_VIN: C6.1 C38.1 C39.1 D1.A J3.16(B8) J7.1
PA_BOOST: L12.1 U1.41(PA_BOOST)
PA_BOOST_EXT: C1.1 C2.1 C47.1 L1.2
POWER_EN: R551.1 U6.31(ADC0_SE7B/PTD6/SPI0_PCS3/UART0_RX/FTM0_CH6/FTM0_FLT0/LLWU_P15)
PTA0/SWD_CLK: J35.1 SH1.2 TP36.1(PIN1) U1.10(PTA0/SWD_CLK)
PTA1/UART0_RX: J41.2 R89.2 SH15.2 TP113.1(PIN1)
PTA2/UART0_TX: J42.1 R88.2 SH16.2 TP114.1(PIN1)
PTA3/SWD_DIO: J14.2(B1) R25.1 R92.2 SH7.2 TP32.1(PIN1) U1.11(PTA3/SWD_DIO)
PTA4/NMI: C53.1 R133.1 R558.2 SW4.1 TP29.1(PIN1) U1.12(PTA4/NMI_B)
PTA18: SH45.2 U1.15(PTA18/EXTAL0)
PTA19: J10.2 R136.1 TP115.1(PIN1) U1.16(PTA19/XTAL0)
PTB0: R29.2 R132.1 TP120.1(PIN1) U1.17(PTB0)
PTB1: J18.4 R28.2 SH11.2 TP121.1(PIN1) U1.18(PTB1)
PTB2: R91.2 SH12.2 TP123.1(PIN1) U1.21(PTB2)
PTB17: R90.2 SH14.2 TP122.1(PIN1) U1.22(PTB17)
PTC1: R97.2 SH10.2 TP112.1(PIN1)
PTC1/RTC_IN: R96.1 R97.1 U1.24(PTC1/ADC0_SE15)
PTC2: C52.1 R557.2 SH9.2 SW3.1 TP24.1(PIN1) U1.25(PTC2/ADC0_SE11)
PTC3: SH40.2 U1.26(PTC3)
PTC4: SH41.2 U1.23(PTC4/DISABLED)
PTD4/SPI1_PCS0: SH3.2 U1.27(PTD4)
PTD5/SPI1_SCK: SH6.2 U1.28(PTD5)
PTD6/LLWU_P15: C51.1 R134.1 R556.2 SW1.1 TP23.1(PIN1) U1.29(PTD6)
PTD7: C54.1 R559.2 SH8.2 SW2.1 TP30.1(PIN1) U1.31(PTD7)
PTE0/SPI1_MISO: J44.1 U1.32(PTE0/DISABLED)
PTE1/SPI1_MOSI: J43.2 U1.34(PTE1)
PTE16: R11.2 R137.1 TP119.1(PIN1) U1.5(PTE16/ADC0DP1/ADC0_SE1)
PTE17: R30.2 R135.1 U1.6(PTE17/ADC0_DM1/ADC0_SE5A)
PTE18/I2C0_SDA: Q1.S2 R117.2 R119.1 U1.7(PTE18/ADC0_DP2/ADC0_SE2)
PTE19/I2C0_SCL: Q1.S1(S2) R116.2 R118.1 U1.8(PTE19/ADC0_DM2/ADC0_SE6A)
PTE30: R85.1 U1.9(PTE30/DAC_OUT/ADC0_SE23/CMP0_IN4)
RESET_B_TGTMCU: J11.2 U6.21(ADC0_SE9/TSI0_CH6/PTB1/I2C0_SDA/FTM1_CH1/FTM1_QD_PHB)
RESET_B_XCVR: J31.1 R5.1 U1.48(RESET)
RESET_TGTMCU_B: D5.C(CATHODE) J9.3 J14.10(B5) R13.2 R14.2 R124.1 TP35.1(PIN1) U1.33(PTA20/RESET_B) U3.7(B1) U5.7(B1)
RFIO: L9.1 U1.39(RFIO)
RFIO_EXT: C4.1 C7.1 C50.1 C58.1 L2.2
RXTX: R141.1 TP37.1(PIN1) U1.37(RXTX)
SDA_EXTAL: C31.1 U6.17(EXTAL0/PTA18/FTM0_FLT2/FTM_CLKIN0) Y3.3
SDA_JTAG_TCLK: J13.4(B2) TP509.1(PIN1) U6.12(JTAG_TCLK/SWD_CLK/EZP_CLK/TSI0_CH1/PTA0/U\A\R\T\0\_\C\T\S\/U\A\R\T\0\_\C\O\L\/FTM0_CH5)
SDA_JTAG_TDI: J13.8(B4) TP511.1(PIN1) U6.13(JTAG_TDI/EZP_DI/TSI0_CH2/PTA1/UART0_RX/FTM0_CH6)
SDA_JTAG_TDO: J13.6(B3) TP510.1(PIN1) U6.14(JTAG_TDO/TRACE_SWO/EZP_DO/TSI0_CH3/PTA2/UART0_TX/FTM0_CH7)
SDA_JTAG_TMS: J13.2(B1) R107.2 TP508.1(PIN1) U6.15(JTAG_TMS/SWD_DIO/TSI0_CH4/PTA3/U\A\R\T\0\_\R\T\S\/FTM0_CH0)
SDA_LED: D11.C(CATHODE) TP106.1(PIN1) U6.29(PTD4/SPI0_PCS1/U\A\R\T\0\_\R\T\S\/FTM0_CH4/EWM_IN/LLWU_P14)
SDA_RST: J13.10(B5) R52.2 R100.1 TP105.1(PIN1) TP512.1(PIN1) U6.19(R\E\S\E\T\)
SDA_RST_TGTMCU_J_B: J9.1 J11.1 R14.1 R16.2 U3.2(A1)
SDA_SPI0_SCK: U4.12(4A) U6.26(PTC5/SPI0_SCK/LPTMR0_ALT2/I2S0_RXD0/CMP0_OUT/LLWU_P9)
SDA_SPI0_SIN: R112.1 U4.8(3Y) U6.28(CMP0_IN1/PTC7/SPI0_SIN/USB_SOF_OUT/I2S0_RX_FS)
SDA_SPI0_SOUT: U4.2(1A) U6.27(CMP0_IN0/PTC6/SPI0_SOUT/PDB0_EXTRG/I2S0_RX_BCLK/I2S0_MCLK/LLWU_P10)
SDA_SWD_EN: R106.2 U4.10(O\E\3\) U4.13(O\E\4\) U6.16(N\M\I\/E\Z\P\_\C\S\/TSI0_CH5/PTA4/FTM0_CH1/LLWU_P3)
SDA_SWD_OE_B: R105.1 U4.1(O\E\1\) U6.20(ADC0_SE8/TSI0_CH0/PTB0/I2C0_SCL/FTM1_CH0/FTM1_QD_PHA/LLWU_P5)
SDA_USB_CONN_DN: J15.2(P2) R50.1 U12.1(A1)
SDA_USB_CONN_DP: J15.3(P3) R51.1 U11.1(A1)
SDA_USB_DN: R50.2 U6.4(USB0_DM)
SDA_USB_DP: R51.2 U6.3(USB0_DP)
SDA_USB_VOUT33: C26.1 C29.1 C32.1 C66.1 D7.A J13.1(A1) R16.1 R17.1 R19.2 R105.2 R106.1 R107.1 R110.1 TP103.1(PIN1) U3.1(VCCA) U4.4(O\E\2\) U4.14(VCC) U6.1(VDD1) U6.5(VOUT33) U6.7(VDDA) U6.11(VBAT)
SDA_USBSHIELD: J15.S1(SHLD1) J15.S2(SHLD2) J15.S3(SHLD3) J15.S4(SHLD4) L7.1
SDA_XTAL: C30.1 U6.18(XTAL0/PTA19/FTM1_FLT0/FTM_CLKIN1/LPTMR0_ALT1) Y3.1
SW1_RST_B: C60.1 J9.2 R113.2 SW5.1
SWD_CLK_TGTMCU: J14.4(B2) J35.2 R93.2 TP51.1(PIN1)
SWD_CLK_TGTMCU_R: R93.1 U4.11(4Y)
SWD_DIO_TGTMCU: R92.1 U4.3(1Y) U4.9(3A)
TC_EXTAL_TP: TP102.1(PIN1) U6.10(EXTAL32)
TC_SDA_USB_ID_TP: J15.4(P4) TP100.1(PIN1)
TC_XTAL_TP: TP101.1(PIN1) U6.9(XTAL32)
UART1_CTS_TGTMCU: R90.1 U6.22(ADC0_SE15/TSI0_CH14/PTC1/SPI0_PCS3/U\A\R\T\1\_\R\T\S\/FTM0_CH0/I2S0_TXD0/LLWU_P6)
UART1_RST_TGTMCU: R91.1 U6.23(ADC0_SE4B/CMP1_IN0/TSI0_CH15/PTC2/SPI0_PCS2/U\A\R\T\1\_\C\T\S\/FTM0_CH1/I2S0_TX_FS)
UART1_RX_TGTMCU: R89.1 U6.25(PTC4/SPI0_PCS0/UART1_TX/FTM0_CH3/CMP1_OUT/LLWU_P8)
UART1_TX_TGTMCU: R88.1 U6.24(CMP1_IN1/PTC3/SPI0_PCS1/UART1_RX/FTM0_CH2/I2S0_TX_BCLK/LLWU_P7)
V_EXT: D2.A J28.1
V_MCU: C27.1 C35.1 C42.1 C43.1 C59.1 J14.1(A1) J40.1 R5.2 R9.2 R13.1 R18.2 R25.2 R113.1 SH42.1 TP6.1(PIN1) U1.19(VDD#19) U1.55(VDD#55) U3.8(VCCB) Y4.1(VIO) Y4.12(VCC)
V_RF: C19.1 C25.1 J47.1 TP13.1(PIN1) U1.35(VBAT2) U1.43(VBAT1)
VR_ANA: C44.1 TP46.1(PIN1) U1.44(VR_ANA)
VR_DIG: C28.1 TP48.1(PIN1) U1.45(VR_DIG)
VR_PA: C14.1 C16.1 C17.1 C18.1 L10.1 L11.1 U1.42(VR_PA)
VTRG_EN: R108.2 R109.1 R551.2 U7.3(ENABLE)
VTRG_FAULT_B: R110.2 U6.32(PTD7/CMT_IRO/UART0_TX/FTM0_CH7/FTM0_FLT1) U7.4(F\A\U\L\T\)
XCVR-SPI_CLK: TP38.1(PIN1) U1.59(SCK/PTC5)
XCVR-SPI_MISO: TP39.1(PIN1) U1.57(MISO/PTC7)
XCVR-SPI_MOSI: TP41.1(PIN1) U1.60(MOSI/PTC6)
XCVR-SPI_SS_B: TP40.1(PIN1) U1.58(NSS/PTD0)
XTAL_32M: SH44.1 U1.47(XTB)
N23353475: C20.2 J5.1
N23353504: C22.1 SH44.2 Y1.3
N23486779: TP108.1(PIN1) U4.6(2Y)
N23497733: C34.2 U7.5(CSLEW)
N23735993: J3.10(B5) R140.2
N23736069: J3.6(B3) SH13.1
N23818123: C40.1 D6.A J7.3
N23859389: J1.3(A2) R122.2
N23859394: J1.5(A3) R123.2
N23859399: J1.7(A4) R129.2
N23868552: J42.2 U1.13(PTA2/DISABLED)
N23868554: J41.1 U1.14(PTA1/DISABLED)
N23869363: C36.1 R9.1 U1.56(VDDA)
N23870337: C13.1 C15.1 L9.2 L11.2
N23870339: C11.2 C13.2 C46.1 L5.1
N23870349: C7.2 C9.1 C11.1 L2.1 L5.2
N23870369: C1.2 C3.1 C8.1 L1.1 L3.2
N23870499: C10.1 C12.2 L10.2 L12.2
N23870540: C8.2 C10.2 C45.1 L3.1
N23886926: J1.9(A5) R130.2
N23887030: J1.11(A6) R131.2
N23913269: J31.2 R85.2
N23918308: D18.A L6.2
N23923482: J4.2(B1) R136.2
N23926816: TP3.1(PIN1) U3.3(A2)
N23926819: TP5.1(PIN1) U3.6(B2)
N23926865: R19.1 U3.5(OE)
N23927016: D5.A(ANODE) R18.1
N23933963: R12.1 TP107.1(PIN1) U4.5(2A)
N23941230: J2.18(B9) Q1.D2 R121.2 R126.2
N23941233: J2.20(B10) Q1.D1(D2) R120.2 R125.2
N23941622: SH6.1 U16.4(A3)
N23941631: SH3.1 U16.7(A6)
N23941634: SH7.1 U16.8(A7)
N23941637: SH1.1 U16.9(A8)
N23943103: SH8.1 U17.1(A1)
N23943106: SH9.1 U17.3(A2)
N23943109: SH10.1 U17.4(A3)
N23943112: SH11.1 U17.5(A4)
N23943115: SH12.1 U17.6(A5)
N23943118: SH14.1 U17.7(A6)
N23943121: SH15.1 U17.8(A7)
N23943124: SH16.1 U17.9(A8)
N23943348: R120.1 U16.20(B1)
N23943351: R121.1 U16.18(B2)
N23958500: R118.2 U16.1(A1)
N23958507: R119.2 U16.3(A2)
N23972508: C47.2 J48.1(CENTER)
N23972666: C58.2 J49.1(CENTER)
N23977839: C55.1 D1.C D10.C J8.3 R3.1 U18.1(VIN)
N23977884: D2.C J8.2 TP33.1(PIN1)
N23977917: D3.C J40.2 J45.2 J46.2 J47.2 R1.2 R6.2 TP31.1(PIN1)
N23977919: J8.1 R1.1
N23978170: D7.C R6.1
N23978250: D4.C(CATHODE) R10.1 TP8.1(PIN1)
N23978332: R3.2 U18.3(ON/O\F\F\)
N23978342: C56.1 U18.4(BYP)
N23993054: D17.1(RED) R11.1 TP18.1(PIN1)
N23993056: D17.4(GREEN) R28.1 TP19.1(PIN1)
N23993058: D17.3(BLUE) R29.1 TP20.1(PIN1)
N24008143: J2.16(B8) R128.1
N24082518: R96.2 Y4.7(OUT)
N24091032: C50.2 C67.1 L4.1
N24091265: ANT1.2(FEED) C68.1 L4.2
N24125287: SH42.2 U1.1(VREFH)
N24125299: SH43.2 U1.2(VREFL)
N24162373: TP15.1(PIN1) U5.6(B2)
N24162382: R20.1 U5.5(OE)
N24162397: R21.2 R124.2 SH13.2 U5.2(A1)
N24165182: D12.A J3.8(B4) R127.2
N24184722: J44.2 U16.5(A4)
N24184751: J43.1 U16.6(A5)
N24196405: D8.C(CATHODE) R30.1 TP17.1(PIN1)
N24206241: J1.1(A1) R141.2
N234833070: D11.A(ANODE) R17.2
N241623790: TP14.1(PIN1) U5.3(A2)

Pads without a net: J1 13 15; J2 1 3 5 7 9 11 13 15 17 19; J3 1 2 3 5 7 9 11 13 15; J4 1 3 5 7 9 11; J13 7 9; J14 6 7 8 9; U1 30; U6 30; Y4 2 3 4 5 8 9 10 11

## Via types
v1: diameter 0.508, hole 0.254, TOP to BOTTOM, 653 vias
v2: diameter 0.457, hole 0.203, TOP to BOTTOM, 8 vias
v3: diameter 0.889, hole 0.457, TOP to BOTTOM, 2 vias

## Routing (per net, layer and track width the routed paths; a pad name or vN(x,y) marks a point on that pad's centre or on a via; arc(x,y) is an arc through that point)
5V_USB: length 33.9
  TOP w0.508: v1(30.06,23.65) 28.41,23.65 27.9,23.14 27.9,20.35 26.89,19.33 24.6,19.33 24.11,18.84 D9.A 22.82,17.81 22.31,17.3 D10.A ; U7.6 29.85,42.97 v1(30.13,42.69)
  BOTTOM w0.508: v1(30.13,42.69) 30.06,42.62 v1(30.06,23.65)
GND: length 202.8
  TOP w0.203: U5.4 6.2,24.03 v1(7.07,24.03) ; U1.38 50.27,17.66 ; U1.36 50.38,16.66 ; C32.2 20.03,42.7 ; C32.2 20.03,44.22 ; C32.2 19.39,43.46 ; U3.4 21.7,20.09 v1(22.31,20.09) ; U1.40 49.91,18.66 49.87,18.69 49.88,18.69 49.88,18.7 v1(49.87,18.7) ; v1(41.88,10.02) 41.84,10.06 v1(38.19,10.06) ; C43.2 v1(47.7,11.33) ; U1.4 44.82,18.16
  TOP w0.254: v1(24.85,40.67) 24.58,40.94 U6.2 ; C43.2 46.84,11.44 U1.20 ; R109.2 22.31,45.23 21.76,45.23 ; U6.8 21.58,40.89 v1(21.81,40.67)
  TOP w0.279: 66.45,26.57 66.45,27.08 66.47,27.08 ; 66.47,27.08 C68.2 ; 66.47,27.08 66.47,27.58 ; 66.45,24.79 C67.2 ; 66.45,24.79 66.45,25.3 ; 66.45,24.79 66.45,24.28
  TOP w0.292: v1(12.92,33.87) 12.73,34.06 ; v1(12.92,35.27) 12.73,35.08
  TOP w0.305: v1(56.35,11.52) 56.25,11.41 Y4.6 ; U17.11 59.78,42.01 v1(59.78,40.67) ; U16.11 48.6,42.01 48.6,40.67 v1(48.6,40.67)
  TOP w0.381: C9.2 58,16.15 58.06,16.22 58.06,17.11 v1(58.13,17.17)
  TOP w0.406: U4.7 37.47,36.65 v1(37.68,36.86)
  TOP w0.457: C12.1 v1(55.65,20.22) ; v1(58,19.15) 58,19.14 57.13,19.14 C18.2 57.37,19.16 C17.2 ; C57.2 v1(10.25,13.74) ; C14.2 57.37,18.16 C16.2 57.11,18.19 58,18.19 v1(58,18.15) ; C45.2 v1(55.71,22.57) ; C46.2 55.71,16.15 v1(54.95,16.15) ; v1(55.64,17.18) 55.65,17.18 55.65,17.17 C15.2 ; C4.2 v1(60.29,17.17) ; C2.2 v1(60.29,22.57) ; C3.2 v1(58,22.57)
  TOP w0.508: 11.92,44.46 TP507.1 11.92,46.53 ; C44.2 v1(53.3,23.39) ; 44.79,24.92 v1(44.79,24.16) ; v1(35.39,10.82) 35.39,9.88 C6.2 36.16,9.88 v1(36.16,10.82) ; v1(9.23,32.28) 8.8,32.72 J15.5 ; v1(39.49,16.26) 39.59,16.36 R8.2 ; J2.14 23.48,51.63 ; J2.14 21.88,50.03 ; J2.14 23.48,50.03 ; J2.14 21.88,51.63 ; v1(20.66,16.79) 20.66,15.72 C55.2 19.9,15.72 v1(19.9,16.79) ; C35.2 v1(18.25,23.9) ; J5.2 59.65,24.78 ; J5.2 58.13,23.27 ; J5.2 59.65,23.27 ; J5.2 58.13,24.78 ; C33.2 v1(31.97,46) ; 35.99,1.77 J3.12 35.99,3.37 ; C64.2 v1(2.76,24.92) ; C42.2 v1(43.4,23.14) 42.94,23.6 C27.2 ; J28.2 21.04,1.81 ; J28.2 19.53,3.32 ; J28.2 21.04,3.32 ; v1(70.13,51.4) 72.35,51.4 TL2.1 ; C59.2 v1(18.25,22.38) ; v1(13.04,29.62) 11.86,29.62 L7.2 11.86,30.38 v1(13.04,30.38) ; C54.2 v1(9.61,43.97) ; C56.2 v1(19.9,17.81) ; R12.2 v1(34.25,33.81) ; U12.2 10.12,36.73 v1(11.01,36.73) ; v1(27.27,13.36) 26.33,13.36 C40.2 26.33,14.12 v1(27.27,14.12) ; v1(13.04,31.14) 14.69,31.14 J13.5 ; J14.3 v1(36.41,14.5) ; v1(14.31,9.04) 14.31,8.1 C5.2 13.55,8.1 v1(13.55,9.04) ; U18.2 v1(15.96,14.76) ; R10.2 v1(12.41,26.44) ; C30.2 v1(25.36,29.74) ; Y1.2 47.25,26.36 S1.4 ; C19.2 53.05,15.59 53.25,15.39 53.25,15.23 v1(53.51,14.97) ; C63.2 v1(2.76,26.44) ; R100.2 v1(25.62,31.27) ; v1(32.6,10.82) 32.6,9.88 C38.2 31.84,9.88 v1(31.84,10.82) ; C31.2 v1(19.77,36.09) ; v1(50.89,24.16) C28.2 49.45,23.39 Y1.4 ; v1(25.98,43.75) 25.51,44.22 C26.2 ; SW4.2 v1(2.63,7.14) ; v1(34.38,10.82) 34.38,9.88 C39.2 33.62,9.88 v1(33.62,10.82) ; 25.88,11.45 J7.2 25.88,9.94 ; C49.2 v1(15.46,40.92) ; v1(11.01,32.66) 10.12,32.66 U11.2 ; C60.2 v1(7.33,15.52) ; C52.2 v1(7.33,8.41) ; C41.2 v1(46.44,33.81) ; C37.2 v1(15.96,9.04) ; C66.2 v1(17.49,39.14) ; J14.5 v1(36.41,15.77) ; SW1.2 v1(2.63,47.27) ; SW5.2 v1(2.63,16.79) ; C65.2 v1(1.99,27.2) ; C21.2 53.3,25.04 v1(53.3,25.09) ; U10.2 v1(12.41,38.38) ; v1(22.44,32.03) 22.44,33.47 Y3.2 ; SW2.2 v1(2.63,42.7) ; C29.2 v1(18.25,20.85) ; v1(41.87,45.75) C48.2 ; C62.2 v1(53.81,45.75) ; v1(20.28,31.01) 20.28,29.7 20.15,29.57 Y3.4 ; C51.2 v1(7.33,44.67) ; C53.2 v1(7.33,5.36) ; C61.2 v1(61.43,34.82) ; J49.4 72.35,1.1 TL1.1 ; R112.2 v1(39.08,45.75) ; v1(53.3,22.57) C25.2 ; SW3.2 v1(2.63,11.96) ; J13.3 v1(13.04,32.28) ; U7.2 28.41,46.36
  GND w0.508: TP507.1 11.92,44.46 ; TP507.1 9.85,44.46 ; TP507.1 11.92,46.53 ; J3.14 40.13,3.37 ; J3.14 38.53,3.37 ; J3.14 40.13,1.77 ; J3.14 38.53,1.77 ; J28.2 21.04,1.81 ; J28.2 21.04,3.32 ; J28.2 19.53,3.32 ; J28.2 19.53,1.81 ; J7.2 27.39,11.45 ; J7.2 25.88,11.45 ; J7.2 27.39,9.94 ; J7.2 25.88,9.94 ; 21.88,50.03 J2.14 ; J2.14 21.88,51.63 ; J2.14 23.48,51.63 ; J2.14 23.48,50.03 ; 35.99,3.37 J3.12 ; J3.12 35.99,1.77 ; J3.12 37.59,3.37 ; J3.12 37.59,1.77 ; J5.2 59.65,24.78 ; J5.2 59.65,23.27 ; J5.2 58.13,24.78 ; J5.2 58.13,23.27 ; J18.1 52.12,34.35 ; J18.1 50.16,36.31 ; J18.1 52.12,36.31 ; J18.1 50.16,34.35
  BOTTOM w0.508: SH43.1 v1(40.98,22.63) ; 21.88,51.63 J2.14 ; J2.14 23.48,50.03 ; J2.14 21.88,50.03 ; J2.14 23.48,51.63 ; J7.2 27.39,11.45 ; J7.2 27.39,9.94 ; J7.2 25.88,11.45 ; J7.2 25.88,9.94 ; TP10.1 v1(59.78,40.67) ; 19.53,3.32 J28.2 21.04,3.32 ; 37.59,3.37 J3.12 35.99,3.37 ; 58.13,23.27 J5.2 59.65,24.78 ; TP507.1 11.92,46.53 ; TP507.1 9.85,44.46 ; TP507.1 11.92,44.46 ; v1(39.49,16.26) 39.71,16.48 TP11.1 ; TP12.1 v1(10.63,27.71) ; TP9.1 v1(14.95,1.3)
  vias: v1(0.79,44.98) v1(0.79,40.92) v1(0.79,27.2) v1(0.79,24.92) v1(0.79,22.38) v1(0.79,19.84) v1(0.79,14.76) v1(0.79,9.68) v1(1.42,3.84) v1(1.55,49.81) v1(3.01,3.84) v1(3.07,1.87) v1(3.14,51.52) v1(3.77,49.81) v1(3.77,47.27) v1(3.77,44.98) v1(3.77,42.7) v1(3.77,40.92) v1(3.77,9.68) v1(3.77,6.88) v1(4.66,16.79) v1(5.3,3.84) v1(5.3,0.91) v1(5.55,52.48) v1(5.55,50.57) v1(6.31,44.98) v1(6.89,11.43) v1(7.33,18.31) v1(7.33,13.74) v1(7.33,3.84) v1(7.77,52.54) v1(7.84,42.7) v1(7.84,40.92) v1(8.09,0.79) v1(9.74,20.6) v1(9.74,18.31) v1(9.99,23.14) v1(11.39,27.71) v1(11.96,52.54) v1(12.92,46.76) v1(12.92,43.97) v1(13.55,23.14) v1(13.55,19.2) v1(13.55,10.19) v1(13.93,52.54) v1(13.93,49.56) v1(14.19,0.79) v1(14.95,3.33) v1(15.46,35.33) v1(15.84,38.13) v1(15.96,12.85) v1(16.09,23.14) v1(16.47,52.54) v1(17.23,45.53) v1(17.74,0.79) v1(18.76,12.85) v1(19.01,52.54) v1(21.04,44.48) v1(21.55,52.54) v1(21.81,39.9) v1(21.81,39.14) v1(21.81,38.38) v1(21.81,37.62) v1(22.19,3.84) v1(22.44,35.33) v1(22.57,40.67) v1(22.57,39.9) v1(22.57,39.14) v1(22.57,38.38) v1(22.57,37.62) v1(23.33,40.67) v1(23.33,39.9) v1(23.33,39.14) v1(23.33,38.38) v1(23.33,37.62) v1(24.03,47.49) v1(24.09,52.54) v1(24.09,40.67) v1(24.09,39.9) v1(24.09,39.14) v1(24.09,38.38) v1(24.09,37.62) v1(24.09,20.09) v1(24.09,9.04) v1(24.35,29.24) v1(24.85,39.9) v1(24.85,39.14) v1(24.85,38.38) v1(24.85,37.62) v1(25.36,3.84) v1(26.38,20.09) v1(26.38,12.34) v1(26.56,47.46) v1(26.63,52.54) v1(27.14,22.12) v1(27.9,19.33) v1(27.9,17.81) v1(27.9,2.06) v1(28.92,28.35) v1(29.17,52.54) v1(29.3,30.51) v1(30.51,46.12) v1(31.33,14.5) v1(31.71,52.54) v1(31.71,6.63) v1(32.6,27.97) v1(32.73,23.65) v1(32.73,21.11) v1(32.98,2.06) v1(34.25,52.54) v1(34.25,44.73) v1(34.76,23.65) v1(34.76,21.11) v1(35.39,29.74) v1(35.39,6.63) v1(36.28,23.65) v1(36.28,21.11) v1(36.54,52.54) v1(38.19,26.31) v1(38.19,22.76) v1(38.19,19.71) v1(38.19,16.79) v1(38.19,13.74) v1(39.08,52.54) v1(41.55,26.31) v1(41.87,52.54) v1(41.86,13.42) v1(44.03,37.87) v1(44.15,34.89) v1(44.28,2.57) v1(44.41,52.54) v1(45.3,26.31) v1(45.3,18.69) v1(45.31,17.17) v1(45.32,15.77) v1(45.32,14.25) v1(45.55,5.11) v1(46.06,17.93) v1(46.09,15.01) v1(46.44,10.06) v1(46.82,18.69) v1(46.82,17.17) v1(46.85,15.77) v1(46.85,14.25) v1(46.95,52.54) v1(47.97,10.06) v1(48.22,26.31) v1(48.35,18.69) v1(48.35,17.2) v1(49.03,18.03) v1(49.49,52.54) v1(49.82,16.95) v1(51.14,45.24) v1(51.65,26.31) v1(51.78,10.06) v1(52.03,52.54) v1(53.05,27.77) v1(54.04,30.26) v1(54.06,10.06) v1(54.14,27.77) v1(54.57,52.54) v1(54.57,26.31) v1(54.95,22.57) v1(55.33,14.63) v1(56.35,7.9) v1(56.73,14.63) v1(57.11,52.54) v1(57.11,0.79) v1(57.62,40.67) v1(57.62,24.03) v1(58,26.31) v1(58,10.06) v1(58.13,14.63) v1(59.65,52.54) v1(59.67,25.01) v1(59.65,0.79) v1(59.78,45.75) v1(59.91,12.98) v1(59.91,11.2) v1(60.29,19.15) v1(60.29,18.15) v1(60.67,42.89) v1(61.62,47.52) v1(61.68,25.62) v1(61.68,22.76) v1(61.68,19.71) v1(61.68,16.79) v1(61.68,13.74) v1(61.68,11.96) v1(61.68,10.06) v1(61.68,5.11) v1(61.94,0.79) v1(62.19,40.35) v1(62.7,52.54) v1(63.08,19.71) v1(63.08,16.54) v1(63.08,13.74) v1(63.08,11.2) v1(63.08,8.85) v1(63.08,6.38) v1(63.46,40.35) v1(63.46,37.81) v1(63.46,35.27) v1(63.46,32.85) v1(63.46,28.09) v1(63.46,25.93) v1(63.46,23.71) v1(63.45,22.18) v1(63.72,42.89) v1(64.1,46.32) v1(64.35,19.71) v1(64.41,18.19) v1(64.41,12.41) v1(65.37,45.94) v1(65.37,20.47) v1(65.75,40.35) v1(65.75,37.81) v1(65.75,35.27) v1(65.75,32.73) v1(65.75,30.19) v1(65.75,28.09) v1(65.75,25.93) v1(65.75,23.65) v1(65.75,22.12) v1(65.75,16.54) v1(65.75,13.74) v1(65.75,11.2) v1(65.75,8.85) v1(66.19,42.51) v1(67.02,52.54) v1(67.02,39.08) v1(67.02,36.41) v1(67.02,33.93) v1(67.02,31.52) v1(67.02,29.04) v1(67.08,6.38) v1(67.72,44.86) v1(68.16,48.09) v1(68.29,43.52) v1(68.29,40.35) v1(68.29,37.81) v1(68.29,35.27) v1(68.29,32.73) v1(68.29,30.19) v1(68.29,28.09) v1(68.29,13.74) v1(68.29,11.2) v1(68.22,3.58) v1(68.35,25.93) v1(68.35,23.71) v1(68.35,20.47) v1(68.35,16.54) v1(68.8,8.92) v1(69.11,4.72) v1(69.11,2.18) v1(69.75,46.19) v1(70.13,48.86) v1(70.38,7.14) v1(70.38,3.58) v1(71.08,43.52) v1(71.21,8.92) v1(72.1,49.11) v1(72.1,46.63) v1(72.92,7.14) v1(72.92,3.58) v1(73.62,43.52) v1(74.51,51.65) v1(74.51,49.11) v1(74.51,46.63) v1(75.46,7.14) v1(75.46,3.58) v1(76.16,43.52) v1(77.05,49.11) v1(77.05,46.63) v1(78,7.14) v1(78,3.58) v1(78.17,51.08) v1(78.17,44.73) v1(78.17,8.53) v1(78.17,2.18) v1(79.59,49.11) v1(79.59,46.63) v1(79.69,51.08) v1(79.69,44.73) v1(79.69,8.53) v1(79.69,2.18) v1(80.54,7.14) v1(80.54,3.58) v1(81.22,51.08) v1(81.22,44.73) v1(81.22,8.53) v1(81.22,2.18) v1(82.13,49.11) v1(82.13,46.63)
P3V3: length 74.4
  TOP w0.508: C37.1 15.96,6.12 ; 15.96,6.12 v1(15.96,5.36) R127.1 17.74,4.34 D12.C ; 15.96,6.12 13.93,6.12 ; R128.2 19.55,45.14 19.55,45.14 18.99,44.58 18.98,44.58 18.55,44.15 18.55,42.87 16.6,40.91 16.6,39.01 17.66,37.95 17.67,37.95 17.76,37.86 17.76,37.85 18.88,36.73 18.88,28.4 v1(18.93,28.35) ; 13.93,6.12 C5.1 ; 13.93,6.12 12.79,6.12 12.15,6.76 11.26,6.76 J46.1 ; R138.2 v1(30.44,17.04)
  BOTTOM w0.508: C37.1 21.3,6.38 22.06,7.14 22.06,13.49 23.08,14.5 25.36,14.5 27.9,17.04 v1(30.44,17.04) 30.44,21.87 28.66,23.65 28.66,27.58 27.89,28.36 18.94,28.36 v1(18.93,28.35)
  BOTTOM w0.762: C37.1 v1(15.96,5.36)
P3V3_BRD: length 31.2
  TOP w0.203: C63.1 5.4,25.68 U5.8
  TOP w0.305: v1(43.4,34.82) 43.4,36.27 U16.2 ; U17.10 59.78,37.24 60.03,37.49 v1(61.43,37.49) ; U16.10 48.61,34.95 48.48,34.82 v1(48.48,34.82) ; v1(54.57,37.62) 54.58,37.61 U17.2
  TOP w0.457: R117.1 v1(42.25,38.38) ; v1(42.65,34.28) 42.17,33.81 R116.1 ; v1(36.54,28.47) 38,28.47 38.06,28.54 D8.A ; Q1.G2 v1(40.6,29.74) Q1.G1
  TOP w0.508: R558.1 v1(8.34,5.36) ; D17.2 31.23,28.98 v1(32.6,28.98) ; D4.A v1(8.34,22) ; C41.1 v1(48.48,34.82) ; C63.1 v1(3.77,26.44) ; C61.1 v1(61.43,37.49) ; R557.1 v1(8.34,8.41) ; R559.1 v1(11.9,43.21) ; R556.1 v1(8.34,44.67) ; C65.1 v1(3.77,27.97)
  PWR w0.508: 10.92,24.12 J45.1 ; J45.1 10.92,22.16 ; J45.1 12.88,24.12 ; J45.1 12.88,22.16
  BOTTOM w0.457: v1(42.65,34.28) 42.17,33.81 R116.1
P3V3_LDO: length 5.2
  TOP w0.635: 12.66,13.81 C57.1 ; 12.66,13.81 v1(12.66,14.88) 12.66,15.77 D3.A ; 12.66,13.81 U18.5
  BOTTOM w0.508: C57.1 v1(12.66,14.88)
P5V: length 5.2
  TOP w0.508: 26.01,16.28 R140.1 R139.2
  TOP w0.813: D6.C D9.C
P5V0_SDA_USB_CONN_VBUS: length 6.9
  TOP w0.508: L6.1 10.12,40.67 v1(10.12,39.4) 10.12,38.38 U10.1 9.87,38.38 9.23,37.74 9.23,36.47 8.67,35.92 J15.1
P5V_SDA: length 68.8
  TOP w0.254: v1(22.48,42.47) 22.48,42.37 22.58,42.27 U6.6
  TOP w0.305: v1(26.38,27.71) 26.38,33.05 R52.1
  TOP w0.508: U7.1 29.86,45.47 v1(30.1,45.24) C33.1 ; v1(32.75,45.25) 32.75,44.27 32.65,44.18 32.65,44.15 C34.1 ; R108.1 v1(20.41,45.24) ; D18.C 13.68,42.7 C49.1 v3(16.47,42.7)
  BOTTOM w0.305: v3(16.47,42.7) 14.76,42.7 10.37,38.31 10.37,35.19 10.36,35.18 10.36,34.74 10.37,34.73 10.37,31.14 12.22,29.29 12.22,29.25 13.87,27.6 26.27,27.6 v1(26.38,27.71)
  BOTTOM w0.508: 20.41,43.71 v1(20.41,45.24) 22.75,45.24 23.15,45.64 29.7,45.64 v1(30.1,45.24) 30.08,45.24 30.1,45.26 30.11,45.26 30.13,45.24 32.74,45.24 v1(32.75,45.25) ; 20.41,43.71 TP104.1 v3(16.47,42.7) ; 20.41,43.71 21.81,43.71 22.48,43.04 v1(22.48,42.47)
VSSA: length 5.6
  TOP w0.254: U1.3 42.15,18.66 41.76,19.05 39.94,19.05 R8.1
  TOP w0.508: C36.2 R8.1
A1/INT: length 5.8
  TOP w0.152: J4.4 49.56,3.06 50.66,4.16 50.66,6.22 R137.2
A2/INT: length 5.3
  TOP w0.152: J4.6 51.02,3.64 R135.2
A3/INT: length 5.7
  TOP w0.152: R134.2 53.61,6.32 53.61,4.3 54.64,3.27 J4.8
A4/SDA/INT: length 20.6
  TOP w0.152: R133.2 43.4,5.87 43.4,2.57 45.05,0.91 55.52,0.91 J4.10
A5/SCL/INT: length 22.1
  TOP w0.152: J4.12 58.45,3.84 56.35,3.84 55.9,3.39 55.9,1.99 55.21,1.3 48.98,1.3 48.35,1.93 48.35,3.14 47.65,3.84 45.68,3.84 44.92,4.6 R132.2
D0/RX/INT: length 10
  TOP w0.152: U17.12 59.13,46.12 60.86,47.84 60.86,49.68 J1.2
D1/TX/INT: length 10.1
  TOP w0.152: U17.13 58.48,43.17 57.81,43.85 57.81,46.63 58.64,47.46 58.64,49.43 57.24,50.83 J1.4
D2/INT: length 11.9
  TOP w0.152: J1.6 55.71,49.75 57.49,49.75 58.32,48.92 58.32,47.71 57.45,46.84 57.45,43.62 57.83,43.24 U17.14
D3/PWM/INT: length 12.1
  TOP w0.152: J1.8 53.17,49.75 55.27,49.75 56.1,48.92 56.1,47.9 57.09,46.91 57.09,43.3 57.18,43.21 U17.15
D4/INT: length 14.3
  TOP w0.152: U17.16 56.53,43.26 56.73,43.46 56.73,46.76 55.78,47.71 55.78,48.73 55.08,49.43 53.05,49.43 52.73,49.75 50.63,49.75 J1.10
D5/PWM/INT: length 15.3
  TOP w0.152: U17.17 55.88,43.23 55.52,43.59 55.52,46.32 54.95,46.89 54.31,46.89 53.24,47.96 53.24,48.79 52.6,49.43 50.51,49.43 50.19,49.75 48.09,49.75 J1.12
D6/PWM/INT: length 17.2
  TOP w0.152: J1.14 45.55,49.75 47.65,49.75 47.97,49.43 50.06,49.43 50.83,48.67 50.83,47.93 51.55,47.21 53.53,47.21 54.16,46.57 54.7,46.57 55.23,46.04 U17.18
D7/CMP/INT: length 17.9
  TOP w0.152: J1.16 43.01,49.75 45.11,49.75 45.43,49.43 47.52,49.43 48.29,48.67 48.29,47.84 48.92,47.21 50.83,47.21 51.78,46.25 51.78,44.48 52.79,43.46 53.68,43.46 53.93,43.21 U17.20
D8/INT: length 16.3
  TOP w0.152: J2.2 39.78,50.83 40.86,49.75 42.57,49.75 42.95,49.36 45.05,49.36 45.75,48.67 45.75,48.09 47.14,46.7 47.14,43.84 47.96,43.03 U16.12
D9/INT: length 18.2
  TOP w0.152: U16.13 47.31,43.1 46.76,43.65 46.76,46.58 46.14,47.21 44.09,47.21 43.21,48.09 43.21,48.6 42.44,49.36 40.22,49.36 39.84,49.75 36.46,49.75 J2.4
D10/SPI_SS: length 18.9
  TOP w0.152: U16.14 46.66,43.06 46.25,43.46 45.94,43.46 45.43,43.97 45.43,45.36 43.54,47.26 41.25,47.26 39.14,49.36 36.35,49.36 35.97,49.75 33.92,49.75 J2.6
D11/MOSI: length 21.2
  TOP w0.152: J2.8 31.38,49.75 33.43,49.75 33.81,49.36 35.9,49.36 36.66,48.6 36.66,47.71 37.4,46.98 43.37,46.98 45.05,45.3 45.05,43.9 46.01,42.94 U16.15
D12/MISO: length 23.4
  TOP w0.152: J2.10 28.84,49.75 30.95,49.75 31.33,49.36 33.36,49.36 34.12,48.6 34.12,47.52 34.95,46.7 43.21,46.7 44.67,45.24 44.67,43.84 45.36,43.15 U16.16
D13/SCK: length 25.2
  TOP w0.152: J2.12 26.68,49.36 30.82,49.36 31.58,48.6 31.58,47.83 33.06,46.36 43.05,46.36 44.28,45.12 44.28,43.59 44.71,43.16 U16.17
DIO0: length 48.7
  TOP w0.152: v1(51.97,32.85) 51.97,34 52.48,34.51 52.48,39.83 53.31,40.67 v1(56.1,40.67) ; U1.49 47.84,21.61 v1(47.84,21.62) ; R122.1 v1(56.1,43.97)
  BOTTOM w0.152: SH40.1 46.7,9.57 47.03,9.9 47.03,11.05 45.95,12.14 42.83,12.14 42.51,12.46 42.51,12.92 43,13.41 43.83,13.41 46.32,15.91 46.32,17.37 46.57,17.61 46.57,18.25 46.32,18.5 46.32,19.33 47.84,20.85 v1(47.84,21.62) 48.84,22.61 48.84,25.22 51.65,28.03 51.65,32.54 v1(51.97,32.85) ; v1(56.1,43.97) TP49.1 v1(56.1,40.67)
DIO1: length 47.3
  TOP w0.152: U1.50 47.34,21.1 v1(47.33,21.11) ; R123.1 v1(53.05,43.97) ; J18.2 52.2,38.93 52.2,40.81 v1(53.37,41.98)
  BOTTOM w0.152: v1(53.05,43.97) TP47.1 53.05,42.3 v1(53.37,41.98) ; SH41.1 46.25,8.15 45.99,8.42 45.99,11.54 45.67,11.86 42.71,11.86 42.23,12.34 42.23,13.14 42.78,13.69 43.35,13.69 44.85,15.19 44.85,15.48 44.85,15.49 44.85,17.48 45.87,18.5 45.87,19.65 v1(47.33,21.11) 47.33,21.87 48.56,23.1 48.56,25.33 48.59,25.37 48.59,25.42 51.33,28.16 51.33,33.11 50.13,34.32 50.13,36.86 J18.2
